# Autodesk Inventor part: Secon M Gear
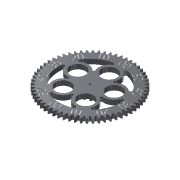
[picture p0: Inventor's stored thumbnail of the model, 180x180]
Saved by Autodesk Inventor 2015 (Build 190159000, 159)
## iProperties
Created: 2015-01
Part Number: Secon M Gear
Material: Generic
Document SubType Name: Modeling
Designer: Steve Brooks
Density: 1 g/cm^3
Appearance: Machined 02
Author: Steve Brooks
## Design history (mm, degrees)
sketch "Sketch1"
  geometry: L1 (-7.367, -0.642)-(-7.367, -0.632); L2 (-69.54, 121.374)-(-69.559, 121.411) reference; L3 (-63.07, 124.46)-(-63.087, 124.498) reference; L4 (-49.691, 129.595)-(-49.704, 129.634) reference; L5 (-56.448, 127.203)-(-56.463, 127.241) reference; L6 (-81.951, 114.209)-(-81.974, 114.244) reference; L7 (-87.859, 110.149)-(-87.883, 110.183) reference; L8 (-118.15, 79.86)-(-118.184, 79.885) reference; L9 (-141.308, 27.851)-(-141.349, 27.859) reference; L10 (-142.615, 20.803)-(-142.656, 20.809) reference; L11 (-132.466, -56.304)-(-132.504, -56.321) reference; L12 (-109.137, -92.231)-(-109.168, -92.258) reference; L13 (-113.792, -86.78)-(-113.825, -86.806) reference; L14 (-81.96, -115.444)-(-81.982, -115.479) reference; L15 (-87.867, -111.384)-(-87.891, -111.417) reference; L16 (-99.004, -102.365)-(-99.032, -102.395) reference; L17 (-93.554, -107.02)-(-93.58, -107.052) reference; L18 (-49.7, -130.833)-(-49.713, -130.872) reference; L19 (-56.457, -128.44)-(-56.472, -128.478) reference; L20 (-21.703, -136.785)-(-21.707, -136.826) reference; L21 (-35.857, -134.542)-(-35.866, -134.583) reference; L22 (-28.809, -135.849)-(-28.816, -135.89) reference; L23 (34.918, -130.836)-(34.931, -130.875) reference; L24 (41.675, -128.443)-(41.69, -128.482) reference; L25 (84.224, -102.371)-(84.252, -102.402) reference; L26 (78.773, -107.026)-(78.799, -107.059) reference; L27 (67.179, -115.45)-(67.201, -115.484) reference; L28 (73.086, -111.39)-(73.111, -111.423) reference; L29 (107.438, -75.194)-(107.472, -75.216) reference; L30 (103.377, -81.101)-(103.411, -81.125) reference; L31 (94.358, -92.238)-(94.389, -92.266) reference; L32 (99.013, -86.788)-(99.046, -86.814) reference; L33 (120.433, -49.691)-(120.472, -49.706) reference; L34 (114.604, -62.783)-(114.64, -62.802) reference; L35 (117.69, -56.313)-(117.727, -56.33) reference; L36 (117.694, 55.063)-(117.732, 55.08) reference; L37 (120.437, 48.441)-(120.475, 48.456) reference; L38 (94.365, 90.99)-(94.395, 91.018) reference; L39 (99.02, 85.539)-(99.052, 85.565) reference; L40 (103.383, 79.852)-(103.417, 79.877) reference; L41 (73.094, 110.143)-(73.119, 110.177) reference; L42 (84.231, 101.124)-(84.259, 101.155) reference; L43 (78.781, 105.779)-(78.807, 105.812) reference; L44 (34.927, 129.592)-(34.94, 129.631) reference; L45 (41.684, 127.199)-(41.699, 127.238) reference; L46 (48.306, 124.456)-(48.323, 124.493) reference; L47 (-35.848, 133.304)-(-35.856, 133.344) reference; L48 (-28.8, 134.61)-(-28.806, 134.651) reference; L49 (90.42, 115.011)-(89.564, 114.423) reference; L50 (89.564, 114.423)-(89.144, 114.122) reference; L51 (89.144, 114.122)-(88.73, 113.816) reference; L52 (88.73, 113.816)-(84.605, 117.157) reference; L53 (84.605, 117.157)-(84.818, 117.626) reference; L54 (84.818, 117.626)-(85.025, 118.099) reference; L55 (85.025, 118.099)-(85.422, 119.059) reference; L56 (85.422, 119.059)-(86.152, 121.025) reference; L57 (86.152, 121.025)-(86.805, 123.047) reference; L58 (86.805, 123.047)-(87.384, 125.121) reference; L59 (87.384, 125.121)-(87.896, 127.24) reference; L60 (87.896, 127.24)-(88.34, 129.403) reference; L61 (88.34, 129.403)-(86.732, 130.571) reference; L62 (86.732, 130.571)-(84.813, 129.479) reference; L63 (84.813, 129.479)-(82.955, 128.338) reference; L64 (82.955, 128.338)-(81.163, 127.146) reference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; 1 further point; 1 other entity
  constraints: 2256 end point, 2 horizontal, 2 vertical, 2299 other
  dimensions: "d153" = 1.04718 dimension on L1.start L141.end L159.end
extrude "Extrusion1" new body sketch "Sketch1" distance "d0" = 18; taper "d1" = 0 deg
sketch "Sketch3"
  geometry: C1 r 0.508 at (7.367, -0.637); C2 r 4 at (-9.833, 13.079); C3 r 4 at (-14.081, -5.533); C4 r 4 at (-2.178, -20.459); C5 r 4 at (16.913, -20.459); C6 r 4 at (28.816, -5.533); C7 r 4 at (24.568, 13.079); C8 r 4 at (7.367, 21.363); C9 r 0.508 at (7.367, -0.637) reference; 1 further point
  constraints: 8 centre point, 2 vertical alignment, 1 coincident, 15 other
  dimensions: "d4" = 8 diameter of C2; "d8" = 360 deg dimension on C1.centre C2.centre (derived); "d41" = 22 distance of C1.centre C8.centre
extrude "Extrusion3" cut sketch "Sketch3" distance "d10" = 10; taper "d11" = 0 deg
sketch "Sketch4"
  geometry: C1 r 0.508 at (7.367, -0.637) reference; C2 r 4 at (7.367, -0.637); 1 further point
  constraints: 1 centre point, 1 coincident
  dimensions: "d12" = 8 diameter of C2
extrude "Extrusion4" cut sketch "Sketch4" stored distance "d13" = 10; taper "d14" = 0 deg
sketch "Sketch5"
  geometry: L1 (-6.374, 160.823)-(-8.361, 160.823) reference; L2 (-7.367, 160.823)-(-7.367, -0.637); L3 (-31.276, 116.957)-(-26.276, 108.297); L4 (11.541, 108.297)-(16.541, 116.957); L5 (-126.564, 13.225)-(-116.778, 15.282); L6 (-105.013, 51.222)-(-111.688, 58.668); L7 (-57.385, -109.717)-(-56.318, -99.774); L8 (-86.863, -77.478)-(-96.008, -81.526); L9 (80.917, -81.914)-(71.79, -77.827); L10 (41.147, -99.988)-(42.171, -109.935); L11 (97.212, 58.21)-(90.505, 50.793); L12 (102.112, 14.802)-(111.889, 12.701); L13 (-7.367, -0.637)-(62.761, 21.979); L14 (-7.367, -0.637)-(-7.206, 73.048); L15 (-7.367, -0.637)-(-77.396, 22.286); L16 (-7.367, -0.637)-(-50.809, -60.155); L17 (-7.367, -0.637)-(35.813, -60.345); C1 r 4 at (-7.367, -0.637) reference; C2 r 30 at (-7.367, 73.048); C3 r 4 at (-7.367, -0.637) reference; C4 r 30 at (-77.396, 22.286); C5 r 30 at (-50.809, -60.155); C6 r 30 at (35.813, -60.345); C7 r 30 at (62.761, 21.979); A1 r 40 centre (-7.367, 73.048) between (-26.276, 108.297) and (11.541, 108.297); A2 r 40 centre (-77.396, 22.286) between (-116.778, 15.282) and (-105.013, 51.222); A3 r 40 centre (-50.809, -60.155) between (-56.318, -99.774) and (-86.863, -77.478); A4 r 40 centre (35.813, -60.345) between (71.79, -77.827) and (41.147, -99.988); A5 r 40 centre (62.761, 21.979) between (90.505, 50.793) and (102.112, 14.802); A6 r 120 centre (-7.367, -0.637) between (-57.385, -109.717) and (42.171, -109.935); A7 r 120 centre (-7.367, -0.637) between (80.917, -81.914) and (111.889, 12.701); A8 r 120 centre (-7.367, -0.637) between (97.212, 58.21) and (16.541, 116.957); A9 r 120 centre (-7.367, -0.637) between (-31.276, 116.957) and (-111.688, 58.668); A10 r 120 centre (-7.367, -0.637) between (-126.564, 13.225) and (-96.008, -81.526); A11 r 73.685 centre (-7.367, -0.637) between (-77.396, 22.286) and (-7.367, 73.048); A12 r 65 centre (-7.367, -0.637) between (-70.256, -17.071) and (-68.008, -24.041); A13 r 65 centre (-7.367, -0.637) between (-11.172, -65.526) and (-3.848, -65.542); A14 r 65 centre (-7.367, -0.637) between (53.17, -24.307) and (55.448, -17.347); A15 r 65 centre (-7.367, -0.637) between (33.851, 49.623) and (27.816, 54.017); A16 r 65 centre (-7.367, -0.637) between (-7.225, 64.362) and (-7.367, 64.363); A17 r 65 centre (-7.367, -0.637) between (-42.551, 54.017) and (-48.365, 49.803); 1 further point
  constraints: 47 point on circle, 32 end point, 22 centre point, 10 coincident, 9 equal length, 8 equal radius, 3 point on line, 1 midpoint, 1 vertical, 16 other
  dimensions: "d15" = 30 deg angle of L3 L2; "d16" = 30 deg angle of L4 L2 (derived); "d17" = 10 radial gap between concentric circles of C2 A1; "d18" = 80 diameter of A1; "d19" = 10 distance of L3.start L3.end; "d42" = 120 radius of A9; "d43" = 120 radius of A8 (derived); "d44" = 120 radius of A7 (derived); "d45" = 120 radius of A6 (derived); "d46" = 120 radius of A10 (derived); "d47" = 60 deg angle of L6 L5; "d48" = 60 deg angle of L7 L8 (derived); "d49" = 60 deg angle of L9 L10 (derived); "d50" = 60 deg angle of L11 L12 (derived); "d53" = 360 deg dimension on L2.end L13.end (derived); "d55" = 30 deg angle of L15 L6 (derived); "d56" = 30 deg angle of L16 L8 (derived); "d57" = 30 deg angle of L10 L17 (derived); "d58" = 30 deg angle of L11 L13 (derived)
extrude "Extrusion5" cut sketch "Sketch5" stored distance "d25" = 10; taper "d26" = 0 deg
sketch "Sketch7"
  geometry: L1 (-6.374, 160.823)-(-8.361, 160.823) reference; L2 (-43.478, 144.381)-(-48.605, 143.008) reference; L3 (-23.51, 146.118)-(8.775, 146.118); L4 (8.775, 146.118)-(8.775, 120.085); L5 (8.775, 120.085)-(-23.51, 120.085); L6 (-23.51, 120.085)-(-23.51, 146.118); L7 (-7.367, -0.637)-(-7.367, 160.823); L8 (-7.367, -0.637)-(-88.098, 139.191); L9 (-7.367, -0.637)-(-147.196, 80.093); L10 (-7.367, -0.637)-(-168.828, -0.637); L11 (-7.367, -0.637)-(-147.196, -81.367); L12 (-7.367, -0.637)-(-88.098, -140.466); L13 (-7.367, -0.637)-(-7.367, -162.098); L14 (-7.367, -0.637)-(73.363, -140.466); L15 (-7.367, -0.637)-(132.461, -81.367); L16 (-7.367, -0.637)-(154.093, -0.637); L17 (-7.367, -0.637)-(132.461, 80.093); L18 (-7.367, -0.637)-(73.363, 139.191); L19 (-85.313, 96.848)-(-98.33, 119.393); L20 (-98.33, 119.393)-(-65.836, 138.154); L21 (-65.836, 138.154)-(-52.82, 115.608); L22 (-52.82, 115.608)-(-85.313, 96.848); L23 (-118.923, 48.171)-(-141.468, 61.188); L24 (-141.468, 61.188)-(-127.96, 84.585); L25 (-127.96, 84.585)-(-105.414, 71.568); L26 (-105.414, 71.568)-(-118.923, 48.171); L27 (-128.618, -11.551)-(-154.651, -11.551); L28 (-154.651, -11.551)-(-154.651, 10.276); L29 (-154.651, 10.276)-(-128.618, 10.276); L30 (-128.618, 10.276)-(-128.618, -11.551); L31 (-106.317, -71.594)-(-128.843, -84.599); L32 (-128.843, -84.599)-(-140.818, -63.857); L33 (-140.818, -63.857)-(-118.292, -50.852); L34 (-118.292, -50.852)-(-106.317, -71.594); L35 (-56.9, -112.175)-(-69.633, -134.228); L36 (-69.633, -134.228)-(-91.928, -121.356); L37 (-91.928, -121.356)-(-79.195, -99.303); L38 (-79.195, -99.303)-(-56.9, -112.175); L39 (2.408, -121.975)-(2.408, -148.009); L40 (2.408, -148.009)-(-17.143, -148.009); L41 (-17.143, -148.009)-(-17.143, -121.975); L42 (-17.143, -121.975)-(2.408, -121.975); L43 (64.654, -98.817)-(77.67, -121.362); L44 (77.67, -121.362)-(54.665, -134.645); L45 (54.665, -134.645)-(41.648, -112.099); L46 (41.648, -112.099)-(64.654, -98.817); L47 (104.887, -52.084)-(124.412, -63.357); L48 (124.412, -63.357)-(112.839, -83.402); L49 (112.839, -83.402)-(93.314, -72.129); L50 (93.314, -72.129)-(104.887, -52.084); L51 (140.479, 11.819)-(113.051, 11.819); L52 (113.051, 11.819)-(113.051, -13.093); L53 (113.051, -13.093)-(140.479, -13.093); L54 (140.479, -13.093)-(140.479, 11.819); L55 (91.21, 73.361)-(111.172, 84.886); L56 (111.172, 84.886)-(125.968, 59.259); L57 (125.968, 59.259)-(106.006, 47.734); L58 (106.006, 47.734)-(91.21, 73.361); L59 (40.429, 113.436)-(51.538, 132.679); L60 (51.538, 132.679)-(78.635, 117.035); L61 (78.635, 117.035)-(67.525, 97.792); L62 (67.525, 97.792)-(40.429, 113.436); L63 (-46.041, 143.695)-(-37.15, 115.608); C1 r 4 at (-7.367, -0.637) reference; C2 r 4 at (-7.367, -0.637) reference; A1 r 120 centre (-7.367, -0.637) between (80.917, -81.914) and (111.889, 12.701) reference; A2 r 120 centre (-7.367, -0.637) between (-31.276, 116.957) and (-111.688, 58.668) reference; 37 further points
  constraints: 37 midpoint, 26 end point, 23 point on line, 1 coincident, 1 point on circle, 75 other
  dimensions: "d62" = 360 deg dimension on A1.centre L7.end (derived)
extrude "Extrusion6" cut sketch "Sketch7" distance "d90" = 2; taper "d91" = 0 deg
sketch "Sketch8"
  geometry: C1 r 4 at (7.367, -0.637) reference; C2 r 4 at (24.568, 13.079) reference; C3 r 4 at (16.913, -20.459) reference; C4 r 4 at (-14.081, -5.533) reference; C5 r 4 at (-9.833, 13.079) reference; C6 r 4 at (-2.178, -20.459) reference; C7 r 4 at (28.816, -5.533) reference; C8 r 4 at (7.367, 21.363) reference; C9 r 30 at (7.367, -0.637); 1 further point
  constraints: 1 centre point, 1 coincident
  dimensions: "d92" = 60 diameter of C9
extrude "Extrusion7" cut sketch "Sketch8" distance "d93" = 3; taper "d94" = 0 deg
sketch "Sketch9"
  geometry: C1 r 4 at (0, 0) reference; C2 r 30 at (0, 0) reference; 1 further point
extrude "Extrusion8" new body sketch "Sketch9" distance "d95" = 4; taper "d96" = 0 deg
sketch "Sketch11"
  geometry: L1 (0, 0)-(0, -22); L2 (0, 0)-(9.545, -19.821); L3 (0, 0)-(17.2, -13.717); L4 (0, 0)-(21.448, -4.895); L5 (0, 0)-(21.448, 4.895); L6 (0, 0)-(17.2, 13.717); L7 (0, 0)-(9.545, 19.821); L8 (0, 0)-(0, 22); L9 (0, 0)-(-9.545, 19.821); L10 (0, 0)-(-17.2, 13.717); L11 (0, 0)-(-21.448, 4.895); L12 (0, 0)-(-21.448, -4.895); L13 (0, 0)-(-17.2, -13.717); L14 (0, 0)-(-9.545, -19.821); C1 r 4 at (0, 0) reference; C2 r 4 at (0, 0) reference; C3 r 30 at (0, 0) reference; C4 r 14.75 at (0, 0); A1 r 22 centre (0, 0) between (0, 22) and (0, -22); A2 r 4 centre (0, -22) between (-3.688, -20.45) and (3.688, -20.45); A3 r 4 centre (17.2, -13.717) between (13.689, -15.634) and (18.288, -9.867); A4 r 4 centre (21.448, 4.895) between (20.758, 0.955) and (19.117, 8.146); A5 r 4 centre (9.545, 19.821) between (12.195, 16.825) and (5.551, 20.025); A6 r 4 centre (-9.545, 19.821) between (-5.551, 20.025) and (-12.195, 16.825); A7 r 4 centre (-17.2, -13.717) between (-18.288, -9.867) and (-13.689, -15.634); A8 r 4 centre (-21.448, 4.895) between (-19.117, 8.146) and (-20.758, 0.955); A9 r 5.558 centre (-8.811, -18.297) between (-3.688, -20.45) and (-13.689, -15.634); A10 r 5.558 centre (8.811, -18.297) between (13.689, -15.634) and (3.688, -20.45); A11 r 5.558 centre (19.799, -4.519) between (20.758, 0.955) and (18.288, -9.867); A12 r 5.558 centre (15.877, 12.662) between (12.195, 16.825) and (19.117, 8.146); A13 r 5.558 centre (0, 20.308) between (-5.551, 20.025) and (5.551, 20.025); A14 r 5.558 centre (-15.877, 12.662) between (-19.117, 8.146) and (-12.195, 16.825); A15 r 5.558 centre (-19.799, -4.519) between (-18.288, -9.867) and (-20.758, 0.955); 26 further points
  constraints: 34 coincident, 32 point on circle, 28 end point, 16 centre point, 15 tangent, 12 equal radius, 1 vertical alignment, 43 other
  dimensions: "d124" = 360 deg dimension on C1.centre L1.end (derived); "d126" = 8 diameter of A2; "d147" = 29.5 diameter of C4
extrude "Extrusion10" new body sketch "Sketch11" distance "d151" = 19; taper "d152" = 0 deg
node "Second gear"
node "Projected Loop1"
node "Gear 7"
node "Spacer"
other parameters: "d20" = 245, "d24" = 115, "d59" = 55, "d153" = 1.04718
